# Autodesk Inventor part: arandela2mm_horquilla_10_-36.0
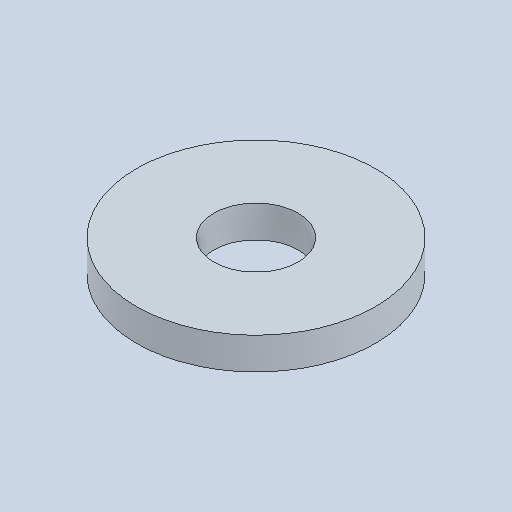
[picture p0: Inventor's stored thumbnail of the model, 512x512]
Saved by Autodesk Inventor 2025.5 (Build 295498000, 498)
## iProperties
Created: 2026-10
Part Number: arandela2mm_horquilla_10_-36.0
Material: Genérico
Document SubType Name: Modeling
Designer: Luis M
Density: 1 g/cm^3
Appearance: Valor por defecto
Author: Luis M
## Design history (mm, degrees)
feature "Base1"
node "Sólido1"
